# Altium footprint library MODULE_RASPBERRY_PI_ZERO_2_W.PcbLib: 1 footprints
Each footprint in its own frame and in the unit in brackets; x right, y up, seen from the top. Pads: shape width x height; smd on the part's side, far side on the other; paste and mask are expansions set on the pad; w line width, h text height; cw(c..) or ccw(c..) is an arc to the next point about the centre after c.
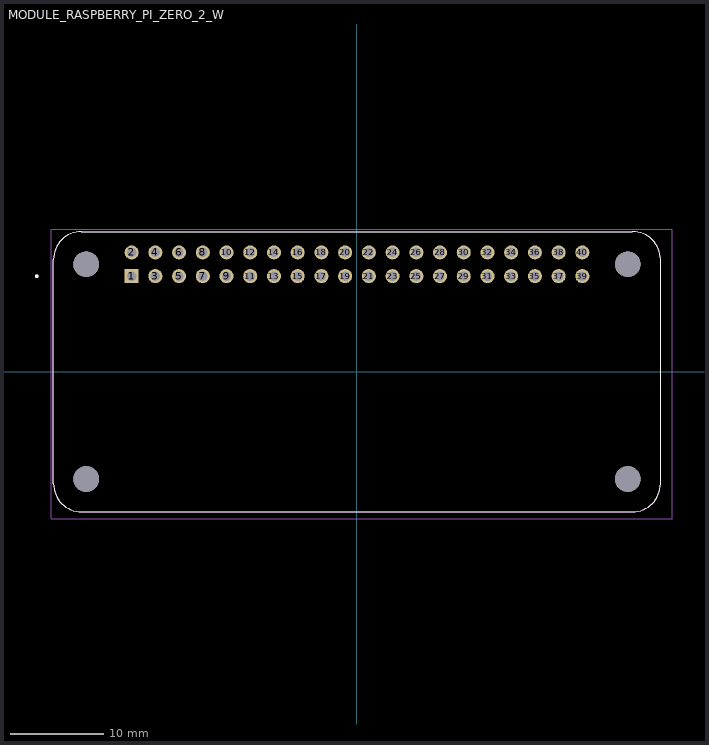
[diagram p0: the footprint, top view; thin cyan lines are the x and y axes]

## MODULE_RASPBERRY_PI_ZERO_2_W [mm]
pads (44):
  rect 1.508x1.508 / inner round 1.508 / far side rect 1.508x1.508 hole 1: 1(-24.13,10.23)
  round 1.508 hole 1: 2(-24.13,12.77) 3(-21.59,10.23) 4(-21.59,12.77) 5(-19.05,10.23) 6(-19.05,12.77) 7(-16.51,10.23) 8(-16.51,12.77) 9(-13.97,10.23) 10(-13.97,12.77) 11(-11.43,10.23) 12(-11.43,12.77) 13(-8.89,10.23) 14(-8.89,12.77) 15(-6.35,10.23) 16(-6.35,12.77) 17(-3.81,10.23) 18(-3.81,12.77) 19(-1.27,10.23) 20(-1.27,12.77) 21(1.27,10.23) 22(1.27,12.77) 23(3.81,10.23) 24(3.81,12.77) 25(6.35,10.23) 26(6.35,12.77) 27(8.89,10.23) 28(8.89,12.77) 29(11.43,10.23) 30(11.43,12.77) 31(13.97,10.23) 32(13.97,12.77) 33(16.51,10.23) 34(16.51,12.77) 35(19.05,10.23) 36(19.05,12.77) 37(21.59,10.23) 38(21.59,12.77) 39(24.13,10.23) 40(24.13,12.77)
  round 2.75 hole 2.75 unplated: ""(-29,-11.5) ""(-29,11.5) ""(29,-11.5) ""(29,11.5)
Top Overlay:
  circle w0.2: c-34.29,10.23 r0.1
  lines w0.127: 4.4,-15 12.75,-15 ; 17,-15 25.35,-15 ; -32.5,-12 ccw(c-29.5,-12) -29.5,-15 29.5,-15 ccw(c29.5,-12) 32.5,-12 32.5,12 ccw(c29.5,12) 29.5,15 -29.5,15 ccw(c-29.5,12) -32.5,12 -32.5,-12
Assembly Top:
  circle w0.2: c-34.29,10.23 r0.1
  lines w0.127: 4.4,-15 12.75,-15 ; 17,-15 25.35,-15 ; -32.5,-12 ccw(c-29.5,-12) -29.5,-15 29.5,-15 ccw(c29.5,-12) 32.5,-12 32.5,12 ccw(c29.5,12) 29.5,15 -29.5,15 ccw(c-29.5,12) -32.5,12 -32.5,-12
Courtyard Top:
  lines w0.05: -32.75,-15.75 33.75,-15.75 33.75,15.25 -32.75,15.25 -32.75,-15.75
3D body "step_temp.STEP": height 4.57, standoff -1.04, extent -32.5,-16 33.5,15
